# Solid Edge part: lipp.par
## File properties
Author: Cymax
Template: Normal.par
Last saved by: Cymax
Revision: 1
Application: Solid Edge
Accuracy: 0,990
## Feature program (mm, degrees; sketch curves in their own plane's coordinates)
sketch for "unnamed Protrusion 1" plane through (0, 0, 0) normal (0, -1, 0) x-axis (1, 0, 0)
  line (-500, -350) -> (500, -350)
  line (500, -350) -> (500, 350)
  line (500, 350) -> (-500, 350)
  line (-500, 350) -> (-500, -350)
extrude "unnamed Protrusion 1" add finite 297.1008 symmetric
replace surface "unnamed ReplaceSurface 1"
replace surface "unnamed ReplaceSurface 2"
Other named dimensions: "OffsetSurface_1": Distance = 10 mm
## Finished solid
Body 1: sheet body, 1 face, 4 edges, 4 vertices.
  Faces by surface: offset 1
  Edges by curve: curve on surface 4
Body 2: sheet body, 2 faces, 7 edges, 6 vertices.
  Faces by surface: plane 1, spline 1
  Edges by curve: line 5, spline 2
Body 3: solid body, 7 faces, 15 edges, 10 vertices.
  Faces by surface: plane 5, offset 1, spline 1
  Edges by curve: line 11, curve on surface 2, intersection 2
Bounding box of the edges (mm; curved faces can reach further): 1000.000 x 135.558 x 700.000, from (-500, -92.5933, -350) to (500, 42.9649, 350).
Planar faces by outward normal: +x 1, +z 1, -x 1, -y 1, -z 1
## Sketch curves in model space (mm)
spline (-490, 0, 0) -> (-71.3954, -0.886, 0) -> (500, -27.0844, 0)
line (-500, 0, 0) -> (-490, 0, 0)
line (-490, 0, 350) -> (-490, 0, -350)
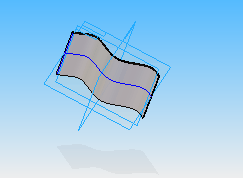
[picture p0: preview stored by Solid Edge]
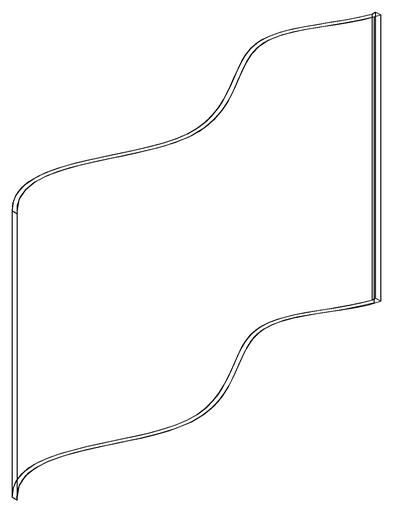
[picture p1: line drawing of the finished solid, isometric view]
